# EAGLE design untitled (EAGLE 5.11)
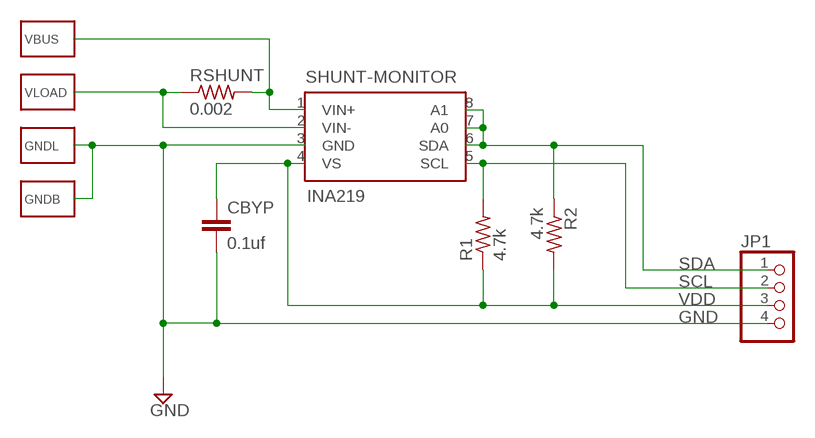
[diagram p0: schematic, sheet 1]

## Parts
CBYP  0.1uf  C-EUC0805  [C0805]
GNDB  WIREPAD-SMD-NO-VALUE  [WIREPAD-SMD]
GNDL  WIREPAD-SMD-NO-VALUE  [WIREPAD-SMD]
JP1  PINHD-1X4  [1X04]
R1  4.7k  R-US_R1210  [R1210]
R2  4.7k  R-US_R1210  [R1210]
RSHUNT  0.002  R-US_R1210  [R1210]
SHUNT-MONITOR  INA219  [8TSOT23]
VBUS  WIREPAD-SMD-NO-VALUE5X5MM  [WIREPAD-SMD-5X5MM]
VLOAD  WIREPAD-SMD-NO-VALUE5X5MM  [WIREPAD-SMD-5X5MM]

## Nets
GND: CBYP.2 GNDB.1(P) GNDL.1(P) JP1.4 SHUNT-MONITOR.3(GND)
N$1: RSHUNT.2 SHUNT-MONITOR.1(VIN+) VBUS.1(P)
N$5: RSHUNT.1 SHUNT-MONITOR.2(VIN-) VLOAD.1(P)
SCL: JP1.2 R1.2 SHUNT-MONITOR.5(SCL)
SDA: JP1.1 R2.1 SHUNT-MONITOR.6(SDA) SHUNT-MONITOR.7(A0) SHUNT-MONITOR.8(A1)
VDD: CBYP.1 JP1.3 R1.1 R2.2 SHUNT-MONITOR.4(VS)

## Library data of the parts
CBYP = resistor:C-EU: CAPACITOR, European symbol
GNDB GNDL VBUS VLOAD = trl:WIREPAD-SMD-NO-VALUE
JP1 = pinhead:PINHD-1X4: PIN HEADER
R1 R2 RSHUNT = resistor:R-US_: RESISTOR, American symbol
SHUNT-MONITOR = trl:INA219

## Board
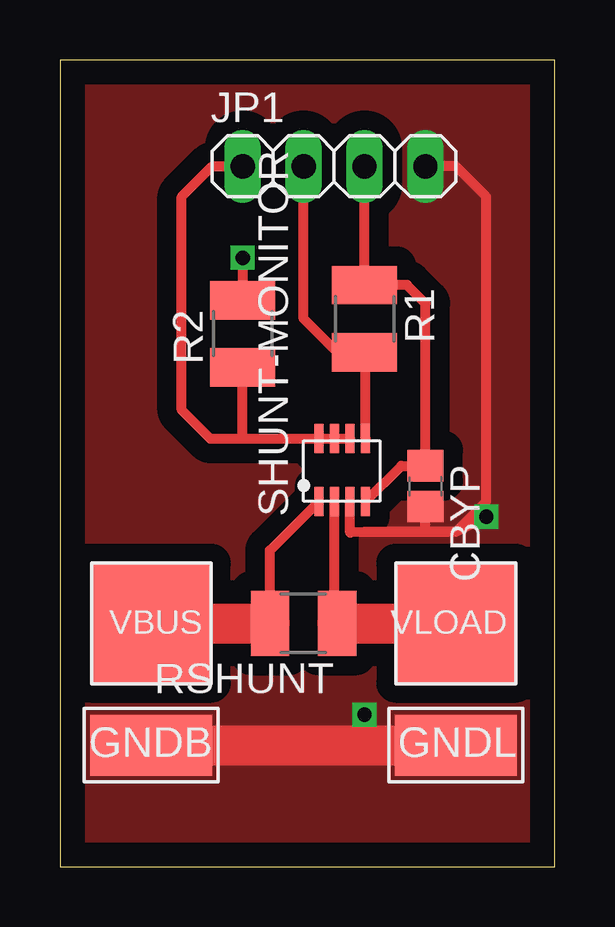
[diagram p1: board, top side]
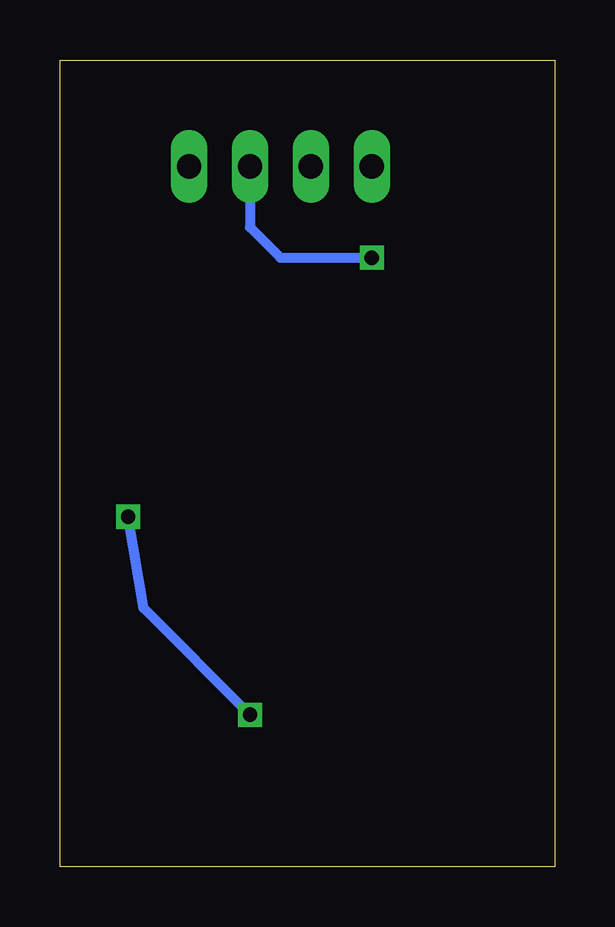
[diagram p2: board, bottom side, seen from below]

Size 20.62 x 33.65 mm. Coordinates in mm from the lower left corner, seen from the top.
Outline: 0,0 20.62,0 20.62,33.65 0,33.65 0,0
Copper layers (1*16): Top 0.035mm / dielectric 1.5mm / Bottom 0.035mm
Design rules "default": minimum track width 10mil, minimum drill 0.6mm, track to track 8mil, track to pad 8mil, pad to pad 8mil, via to via 8mil, smd to smd 8mil, copper to edge 40mil, drill to drill 8mil, minimum pad ring 10mil, minimum via ring 8mil, stop-mask expansion 4mil, vias tented up to drill 0mil, thermal gap 10mil

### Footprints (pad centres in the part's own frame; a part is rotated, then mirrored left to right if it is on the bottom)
C0805 = smd 1.3 x 1.5: 1 -0.85,0; 2 0.85,0
WIREPAD-SMD = smd 2.54 x 5.08: 1 0,0
1X04 = drill 1.016 long: 1 -3.81,0; 2 -1.27,0; 3 1.27,0; 4 3.81,0
R1210 = smd 1.6 x 2.7: 1 -1.4,0; 2 1.4,0
8TSOT23 = smd 0.381 x 1.22: 1 -1.27,-1.27; 2 -0.62,-1.27; 3 0.03,-1.27; 4 0.68,-1.27; 5 0.68,1.35; 6 0.03,1.35; 7 -0.62,1.35; 8 -1.27,1.35
WIREPAD-SMD-5X5MM = smd 5 x 5: 1 0,0

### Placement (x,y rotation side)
CBYP  15.24,15.88 270 top
GNDB  3.81,5.08 90 top
GNDL  16.51,5.08 90 top
JP1  11.43,29.21 0 top
R1  12.7,22.86 270 top
R2  7.62,22.23 90 top
RSHUNT  10.16,10.16 180 top
SHUNT-MONITOR  12.06,16.51 0 top
VBUS  3.81,10.16 90 top
VLOAD  16.51,10.16 90 top

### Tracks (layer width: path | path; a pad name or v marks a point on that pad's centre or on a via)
GND  (via drill 0.6)
  Top 0.406: JP1.4 16.51,29.21 17.78,27.94 17.78,15.24 16.51,13.97 | SHUNT-MONITOR.3 12.1,13.94 12.7,13.97 15.24,13.97 | 16.51,13.97 15.24,13.97 | 15.24,13.97 CBYP.2 | v17.78,14.61 16.51,13.97 | 12.7,5.08 v12.7,6.35
  Top 1.676: GNDB.1 12.7,5.08 GNDL.1
  Bottom 0.406: v17.78,14.61 17.14,10.79 v12.7,6.35
  pour Top (isolate 0.813, no thermals): 0,33.66 20.32,33.66 20.32,0 0,0
N$1
  Top 0.406: RSHUNT.2 8.76,13.21 SHUNT-MONITOR.1
  Top 1.676: VBUS.1 RSHUNT.2
N$5
  Top 0.406: SHUNT-MONITOR.2 11.45,10.28 RSHUNT.1
  Top 1.676: RSHUNT.1 VLOAD.1
SCL
  Top 0.406: SHUNT-MONITOR.5 12.74,21.41 R1.2 11.56,21.46 10.16,22.86 JP1.2
SDA
  Top 0.406: SHUNT-MONITOR.6 SHUNT-MONITOR.7 SHUNT-MONITOR.8 7.62,17.86 | JP1.1 6.35,29.21 5.08,27.94 5.08,19.05 6.27,17.86 7.62,17.86 | 7.62,17.86 R2.1
VDD  (via drill 0.6)
  Top 0.406: SHUNT-MONITOR.4 14.23,16.73 CBYP.1 15.24,23.5 14.47,24.26 R1.1 JP1.3 | v7.62,25.4 R2.2
  Bottom 0.406: v7.62,25.4 11.43,25.4 12.7,26.67 JP1.3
